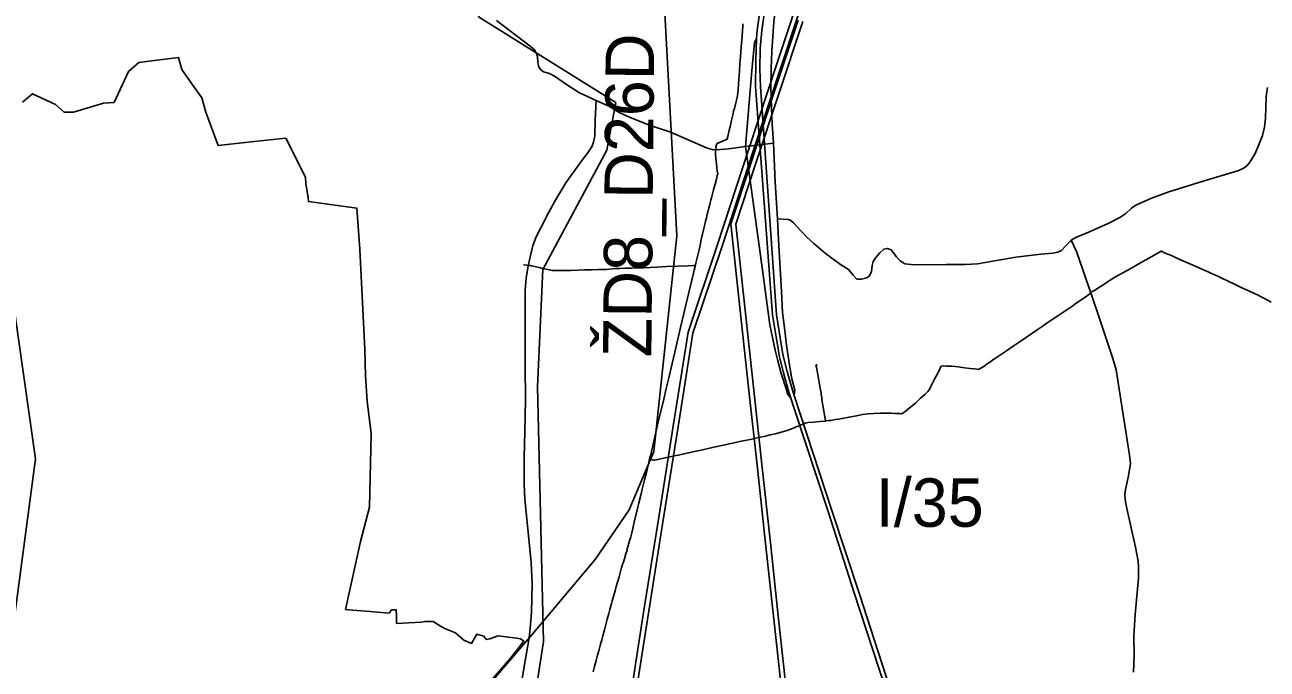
# Model space of a CAD drawing. Extents: x -789162 to -606354, y -1062736 to -945481.
# Drawn here: x -688746 to -684895, y -992137 to -990141 of the extents above; entities that cross this region are included whole.
import ezdxf

# ---------------------------------------------------------------- set-up
doc = ezdxf.new("R2010")
doc.units = 0
for name, color, linetype in [('_SIRSI VZTAHY_CYKLOTRASY MISTNI S', 7, 'Continuous'), ('_SIRSI VZTAHY_ELEKTRICKE VEDENI VN 110 kV S', 7, 'Continuous'), ('_SIRSI VZTAHY_OP vodnich zdroju II stupne', 7, 'Continuous'), ('_SIRSI VZTAHY_SILNICE I a II TRIDY_STAV POPIS', 7, 'Continuous'), ('_SIRSI VZTAHY_SILNICE I TRIDY_STAV', 7, 'Continuous'), ('_SIRSI VZTAHY_SILNICE III TRIDY_STAV', 7, 'Continuous'), ('_SIRSI VZTAHY_VTL PLYNOVOD', 7, 'Continuous'), ('_SIRSI VZTAHY_ZELEZNICE NAVRH', 7, 'Continuous'), ('_SIRSI VZTAHY_ZELEZNICE_NAVRH POPIS', 7, 'Continuous')]:
    doc.layers.add(name, color=color, linetype=linetype)

msp = doc.modelspace()

# ---------------------------------------------------------------- linework, layer by layer
at = {"layer": '_SIRSI VZTAHY_CYKLOTRASY MISTNI S'}
for points in [[(-687483.2, -993028.1), (-687247.3, -992760.3), (-687137.8, -992052), (-687156.9, -991261.1), (-687139.8, -990898.4), (-686941.4, -990528.8), (-686914.1, -990381.7), (-687339.8, -990115.4), (-687139.8, -989851.3), (-686992, -989932.1), (-686499.9, -989984.2), (-686422.9, -989699.9), (-686284.8, -989378.4), (-686007.6, -989239)], [(-688556.1, -989836.5), (-688904.9, -989942.6), (-689006.9, -990177.5), (-688990.4, -990418.2), (-688877.5, -990794.6), (-688784.4, -990982.2), (-688712.6, -991485.2), (-688781.8, -992007.3), (-688812.6, -992131.8), (-688714.4, -992378.9), (-688830.5, -992822.1), (-689079.5, -993178.6), (-688841.2, -993325.5), (-688500.5, -993378.6), (-688063.6, -993516.3), (-687698.6, -993702), (-687435.2, -993863.7)]]:
    msp.add_lwpolyline(points, dxfattribs=at)
at = {"layer": '_SIRSI VZTAHY_ELEKTRICKE VEDENI VN 110 kV S'}
for points in [[(-687451.1, -994051.8), (-687286.8, -993896.2), (-687112.2, -993728.6), (-687063.1, -993431), (-687015, -993140.6), (-686965.9, -992829.5), (-686919.2, -992531.6), (-686876.3, -992269.3), (-686827.9, -991961.7), (-686779.6, -991659.8), (-686736, -991384.3), (-686689.8, -991092.6), (-686599, -990821.5), (-686501.5, -990524.6), (-686415.2, -990261.5), (-686321.1, -989977.3), (-686243.1, -989742.1), (-686159.3, -989488), (-686062.1, -989191.4), (-685979.1, -988943.5), (-685905.5, -988720.6), (-685829.4, -988490.2), (-685756.3, -988268), (-685732.3, -988002.4)], [(-687098.1, -993735.7), (-687048.3, -993433.5), (-687000.2, -993143.1), (-686951.1, -992831.9), (-686904.4, -992534.1), (-686861.5, -992271.8), (-686813.1, -991964.1), (-686764.8, -991662.2), (-686721.2, -991386.8), (-686675.2, -991096.1), (-686584.8, -990826.2), (-686487.3, -990529.2), (-686401, -990266.2), (-686306.9, -989982), (-686228.9, -989746.8), (-686145, -989492.7), (-686047.8, -989196.2), (-685964.9, -988948.3), (-685891.3, -988725.2), (-685815.2, -988494.8), (-685741.5, -988271.1), (-685717.4, -988003.3)], [(-686349, -990126), (-686423, -990349.7), (-686497.1, -990573.9), (-686557.7, -990757.1), (-686529.4, -991016.9), (-686502.4, -991265.1), (-686475.3, -991514.4), (-686450, -991747.7), (-686425.4, -991973.3), (-686402.7, -992181.3), (-686375.2, -992433.8), (-686356.6, -992606.6), (-686325.5, -992891.3), (-686300.1, -993125.2), (-686273.7, -993367.7), (-686249.4, -993590.9)], [(-686349, -990126), (-686423, -990349.7), (-686497.1, -990573.9), (-686557.7, -990757.1), (-686529.4, -991016.9), (-686502.4, -991265.1), (-686475.3, -991514.4), (-686450, -991747.7), (-686425.4, -991973.3), (-686402.7, -992181.3), (-686375.2, -992433.8), (-686356.6, -992606.6), (-686325.5, -992891.3), (-686300.1, -993125.2), (-686273.7, -993367.7), (-686249.4, -993590.9)], [(-686334.7, -990130.7), (-686408.7, -990354.4), (-686482.9, -990578.6), (-686542.4, -990758.7), (-686514.5, -991015.2), (-686487.5, -991263.5), (-686460.4, -991512.7), (-686435, -991746), (-686410.4, -991971.7), (-686387.8, -992179.6), (-686360.3, -992432.1), (-686341.6, -992605), (-686310.6, -992889.6), (-686285.2, -993123.6), (-686258.8, -993366.1), (-686234.5, -993589.2)], [(-686334.7, -990130.7), (-686408.7, -990354.4), (-686482.9, -990578.6), (-686542.4, -990758.7), (-686514.5, -991015.2), (-686487.5, -991263.5), (-686460.4, -991512.7), (-686435, -991746), (-686410.4, -991971.7), (-686387.8, -992179.6), (-686360.3, -992432.1), (-686341.6, -992605), (-686310.6, -992889.6), (-686285.2, -993123.6), (-686258.8, -993366.1), (-686234.5, -993589.2)]]:
    msp.add_lwpolyline(points, dxfattribs=at)
at = {"layer": '_SIRSI VZTAHY_OP vodnich zdroju II stupne'}
msp.add_lwpolyline([(-687328.5, -992205.1), (-687239.4, -992102.3), (-687198.8, -992050.4), (-687209.6, -992043.4), (-687221.7, -992041.3), (-687278.7, -992034.1), (-687304.3, -992043.5), (-687315.5, -992045.7), (-687323.3, -992035.7), (-687345.1, -992029), (-687361.3, -992057.5), (-687384.8, -992048), (-687411, -992024.5), (-687441.8, -992012.8), (-687457.4, -992003.8), (-687480.3, -991989.3), (-687498.3, -991990.1), (-687505.4, -991989.4), (-687516.6, -991991.5), (-687594.3, -991995.5), (-687594.2, -991973.4), (-687594.6, -991953.7), (-687609.2, -991953.7), (-687616.2, -991963.5), (-687665.2, -991960), (-687675.8, -991959.1), (-687742.7, -991953.1), (-687751.8, -991952.3), (-687705.8, -991742.1), (-687677.2, -991635.4), (-687672.7, -991407), (-687684.3, -991307.2), (-687689.5, -991228.9), (-687692.2, -991147.1), (-687707.3, -990835.5), (-687716.3, -990709.3), (-687866.5, -990688.3), (-687867.6, -990675.8), (-687874.7, -990633.6), (-687875.9, -990612.5), (-687893.4, -990578.4), (-687897, -990571.4), (-687936.9, -990491.6), (-688035.5, -990502.7), (-688147, -990515), (-688185.1, -990411.7), (-688197.1, -990366.7), (-688228.6, -990323.2), (-688259, -990279.6), (-688269.5, -990242), (-688352.1, -990252.5), (-688392.7, -990257), (-688424.2, -990285.6), (-688469.3, -990381.8), (-688502.4, -990383.3), (-688595.5, -990411.8), (-688624.1, -990411.8), (-688651.1, -990387.8), (-688721.7, -990354.7), (-688753.3, -990380.3)], dxfattribs=at)
at = {"layer": '_SIRSI VZTAHY_SILNICE I TRIDY_STAV'}
for points in [[(-686465, -990077.6), (-686475.5, -990157.4), (-686478, -990183.3)], [(-686361.2, -991289.1), (-686371.2, -991255.2), (-686382.9, -991215.2), (-686396.5, -991162.1), (-686416.1, -991039.4), (-686466.1, -990332), (-686467.2, -990277.8), (-686466.6, -990213.9), (-686461, -990157.8), (-686450.6, -990077.9)], [(-686478, -990183.3), (-686483.8, -990196), (-686492.1, -990283.6), (-686511.8, -990517.9)], [(-686478, -990183.3), (-686479.6, -990251.6), (-686480.6, -990331.3), (-686428.6, -991039.3), (-686406.9, -991169.8), (-686394.9, -991215.2), (-686377.5, -991278.7), (-686371.7, -991297.6)], [(-686511.8, -990517.9), (-686458.8, -990908.6)], [(-686458.8, -990908.6), (-686436.6, -991070.2), (-686420, -991148.6), (-686412.9, -991177.6), (-686401.3, -991221.5), (-686385.4, -991271.8), (-686381.7, -991285), (-686371.7, -991297.6)], [(-686371.7, -991297.6), (-686361.9, -991326.8), (-686255.6, -991648.6), (-686175.5, -991900.5), (-686079.2, -992193.9), (-686053, -992277.8), (-686041, -992323), (-686028.4, -992380.7), (-686020.2, -992437.3), (-686015.1, -992500.1), (-686014.6, -992512.8)], [(-686002.6, -992506.4), (-686002.8, -992501.9), (-686008.2, -992437.6), (-686014.5, -992385.9), (-686022, -992341.3), (-686034.7, -992287.1), (-686065.4, -992192.7), (-686158.5, -991904.8), (-686243.5, -991648.6), (-686361.2, -991289.1)]]:
    msp.add_lwpolyline(points, dxfattribs=at)
at = {"layer": '_SIRSI VZTAHY_SILNICE III TRIDY_STAV'}
for points in [[(-686094.8, -989270.2), (-686090.6, -989304.6), (-686092.2, -989327.2), (-686099.7, -989348.2), (-686130.8, -989394.2), (-686166.2, -989443.8), (-686190, -989478), (-686213, -989515.3), (-686240.2, -989568.7), (-686254.3, -989597.3), (-686309.8, -989732.6), (-686353.8, -989848), (-686385.5, -989942.6), (-686401.9, -990003.6), (-686413.5, -990057.4), (-686418.6, -990090), (-686423.9, -990131.2), (-686430.7, -990222.5), (-686432.9, -990275.7), (-686433.1, -990332.1), (-686431.8, -990398.7), (-686429.3, -990447.2), (-686425.1, -990507.2)], [(-687284.3, -990127.2), (-687180, -990206.3), (-687165.5, -990219.2), (-687160.5, -990227.3), (-687156.4, -990239.3), (-687155.8, -990256.8), (-687153.3, -990269), (-687147.9, -990279.4), (-687138.6, -990286.5), (-687119.9, -990292), (-687104.3, -990299.6), (-687060.8, -990329.5), (-687026.5, -990351.1), (-686974.6, -990374.7)], [(-685502.3, -990808.5), (-685486, -990798.7), (-685452.6, -990785), (-685385.4, -990755.4), (-685352.3, -990737.4), (-685333.3, -990725.2), (-685315.5, -990708.6), (-685302.2, -990699.8), (-685254.1, -990677.9), (-685200.1, -990657.9), (-685093.9, -990625.1), (-684983.4, -990591.9), (-684966.7, -990584.1), (-684958.5, -990577.9), (-684951.2, -990569.7), (-684933.7, -990541.9), (-684921.8, -990514.4), (-684909.1, -990484.1), (-684903.8, -990457.5), (-684900.7, -990430.2), (-684898.1, -990364.2), (-684896.4, -990347.4), (-684893.6, -990334.6)], [(-686974.6, -990374.7), (-686977.9, -990435.9), (-686979.5, -990484.8), (-686983.3, -990504.3), (-686988.4, -990519.1), (-686999.3, -990534.9), (-687029.4, -990575.4), (-687068.5, -990630.3), (-687099.9, -990682.4), (-687121.2, -990721.7), (-687145.7, -990768), (-687161.4, -990797.7), (-687170.9, -990824.4), (-687186.1, -990887.8), (-687192, -990925.7), (-687194.7, -990962.7), (-687195.2, -991023), (-687194.7, -991198.2), (-687194, -991301.6), (-687195.9, -991402.5), (-687197.9, -991481.1), (-687198, -991565.2), (-687195.9, -991609.8), (-687176.6, -991807), (-687173.5, -991872.8), (-687175.9, -991961.8), (-687179.1, -992010.7), (-687182.8, -992040.8), (-687199.1, -992135.2), (-687211.5, -992211.6)], [(-686974.6, -990374.7), (-686935.4, -990393), (-686903.7, -990412.1), (-686871.9, -990426.7), (-686807.8, -990452.4), (-686747.1, -990471.9), (-686632.5, -990522.2), (-686612.2, -990527.6), (-686589.5, -990527.5), (-686564.8, -990525.3), (-686511.8, -990517.9)], [(-686511.8, -990517.9), (-686425.1, -990507.2)], [(-686425.1, -990507.2), (-686419.9, -990628.1), (-686413.1, -990741.7)], [(-686413.1, -990741.7), (-686378.9, -990743.7), (-686372, -990747.5), (-686363, -990754.6), (-686339.5, -990780.3), (-686321.5, -990798.5), (-686300.6, -990818.1), (-686263.9, -990849.5), (-686217.8, -990883), (-686192.9, -990898.5), (-686178.6, -990916), (-686166.8, -990928.8), (-686152.7, -990928.7), (-686136, -990925), (-686127.6, -990918.6), (-686121.8, -990905.4), (-686119.6, -990886.1), (-686115.9, -990873.7), (-686108.6, -990861.7), (-686096.3, -990848.1), (-686083.6, -990835.8), (-686072.3, -990833.8), (-686060.3, -990838), (-686044.2, -990859.4), (-686032.5, -990872.5), (-686018.4, -990881.4), (-685989.6, -990884.1), (-685890.1, -990883), (-685830.4, -990883.5), (-685793.4, -990881.8), (-685674, -990861.2), (-685596.2, -990851.4), (-685559.5, -990848.5), (-685544.1, -990845.6), (-685532.2, -990839.8), (-685520.3, -990826.6), (-685502.3, -990808.5)], [(-686361.2, -991289.1), (-686358.7, -991273), (-686368.1, -991237.4), (-686374.9, -991201.8), (-686385.2, -991133.5), (-686391.3, -991080), (-686397.4, -991032.2), (-686400.2, -990966.9), (-686410.1, -990807.3), (-686413.1, -990741.7)], [(-685309.7, -992146.9), (-685307.5, -992094.3), (-685308.8, -992033.7), (-685304.4, -991967.6), (-685299.6, -991911.7), (-685293.9, -991855.2), (-685294.2, -991821.9), (-685295.5, -991802.9), (-685303.4, -991759), (-685330.4, -991640), (-685334.5, -991619), (-685336.7, -991598.7), (-685334.1, -991580.5), (-685325.1, -991538.1), (-685318.9, -991500.4), (-685321.9, -991474.6), (-685330.7, -991414.2), (-685343.1, -991335.8), (-685362.8, -991210.1), (-685373.9, -991174.5), (-685421.2, -991032.6), (-685447.2, -990956.8), (-685485.7, -990843.2), (-685502.3, -990808.5)]]:
    msp.add_lwpolyline(points, dxfattribs=at)
at = {"layer": '_SIRSI VZTAHY_VTL PLYNOVOD'}
for points in [[(-686548.8, -990407.7), (-686546.4, -990399.9), (-686541.1, -990378.2), (-686537.9, -990365.5), (-686535.6, -990351.5), (-686533.8, -990327.5), (-686532.7, -990307.3), (-686532.2, -990300.3), (-686530.8, -990282.3), (-686529.3, -990261.9), (-686527.4, -990239.6), (-686525.3, -990209.2), (-686522.7, -990177.2), (-686521.3, -990157.7), (-686520.6, -990146.5), (-686520, -990137.6)], [(-686668, -990887), (-686667.6, -990885.9), (-686667.4, -990885.4), (-686666.9, -990884.1), (-686665.8, -990879), (-686660.6, -990858.7), (-686655.9, -990838.2), (-686653, -990824.9), (-686650.1, -990811.4), (-686647, -990796.7), (-686645.6, -990789.9), (-686645.6, -990789.7), (-686644.2, -990784.8), (-686641.9, -990775.5), (-686639.6, -990763.9), (-686635.6, -990749), (-686632.9, -990738.3), (-686630.4, -990727.8), (-686627.8, -990717.6), (-686625.3, -990708.2), (-686622.4, -990697.4), (-686619.1, -990683.5), (-686617.6, -990677.3), (-686615.4, -990668.4), (-686611.3, -990652.2), (-686606.6, -990634.9), (-686602.4, -990618.6), (-686599.6, -990608.1), (-686598.2, -990602), (-686599.5, -990592.9), (-686600.7, -990582.5), (-686602.8, -990563.6), (-686605.1, -990542.2), (-686605.3, -990540.5), (-686604.6, -990533.1), (-686603.5, -990523.6), (-686603.8, -990519.6), (-686603.9, -990518.5), (-686603, -990515.9), (-686601.4, -990509.1), (-686600.8, -990508.4), (-686594.9, -990506.3), (-686583.2, -990501.4), (-686578.4, -990499.3), (-686569, -990495.1), (-686568.6, -990493.8), (-686567, -990487), (-686562.3, -990467.2), (-686559.7, -990457.2), (-686555, -990436.3), (-686550.4, -990415.1), (-686549, -990408.8), (-686548.8, -990408), (-686548.8, -990407.7)], [(-686548.8, -990407.7), (-686548.9, -990407.6)], [(-684882.6, -990999.7), (-684903.1, -990988.8), (-684915.5, -990982.3), (-684925.4, -990977.9), (-684934.5, -990973.7), (-684949.7, -990966.5), (-684973.2, -990955.3), (-684989.8, -990947.4), (-685004.2, -990940.5), (-685008, -990938.9), (-685015.7, -990935), (-685033.2, -990926.6), (-685047.7, -990920), (-685055.5, -990916.3), (-685065.8, -990912.1), (-685078.4, -990906.1), (-685090.1, -990900.7), (-685110.7, -990891.5), (-685134.9, -990881.2), (-685163.4, -990868.8), (-685183.7, -990860.1), (-685192.1, -990856), (-685211.1, -990847.8), (-685223, -990842.1), (-685223.6, -990841.9), (-685224.2, -990842.2), (-685243.7, -990853.3), (-685262, -990864), (-685280.4, -990874.4), (-685300, -990885.5), (-685321.6, -990897.9), (-685340, -990908.2), (-685355.5, -990916.9), (-685372, -990926.1), (-685380.1, -990930.9), (-685387.2, -990935.4), (-685401.8, -990945.1), (-685416.7, -990955.1), (-685430.8, -990964), (-685437.5, -990967.2), (-685444.2, -990973), (-685448, -990976.1), (-685466.9, -990990.1), (-685486.7, -991003.3), (-685500.9, -991013.2), (-685522.2, -991027.6), (-685543.9, -991042), (-685568.2, -991058.5), (-685576.8, -991064.7), (-685589.7, -991073.5), (-685604.7, -991083.7), (-685621.8, -991095.1), (-685641.4, -991108.2), (-685663.8, -991123.7), (-685682.6, -991136.4), (-685703.1, -991150.6), (-685725.3, -991165.8), (-685740.3, -991176.2), (-685742.3, -991177.3), (-685751.9, -991184), (-685763.5, -991191.7), (-685773.7, -991199.1), (-685786.4, -991206.3), (-685790.9, -991208.3), (-685794.8, -991207.9), (-685801.8, -991207.2), (-685815.5, -991205.9), (-685833.5, -991203.3), (-685853.1, -991200.8), (-685872.6, -991198.9), (-685880.8, -991198.1), (-685884.9, -991198), (-685885, -991198), (-685889.5, -991198), (-685897.1, -991197.9), (-685904, -991198.4), (-685905.7, -991198.6), (-685906.6, -991200), (-685908.6, -991204.6), (-685916.3, -991220.3), (-685924.8, -991237.2), (-685932.1, -991251), (-685938.4, -991263.2), (-685941.8, -991270.6), (-685947, -991276.7), (-685955.3, -991285), (-685970.2, -991299.1), (-685985.6, -991312.9), (-686004.3, -991328.6), (-686018.3, -991340.1), (-686026.1, -991345.6), (-686026.9, -991345.8), (-686027.8, -991345.7), (-686035.1, -991345.1), (-686042.9, -991344.7), (-686049.6, -991344.7), (-686059.1, -991344.1), (-686061.8, -991344.2), (-686063, -991344.2), (-686063.2, -991344.2), (-686065.9, -991344.1), (-686075, -991344), (-686093.4, -991343.9), (-686113.8, -991345.2), (-686131.4, -991346.6), (-686149.4, -991348.6), (-686167.8, -991351.9), (-686190.8, -991356.2), (-686212.1, -991360.7), (-686223.6, -991363), (-686233.6, -991364.2), (-686246.9, -991366.7), (-686253.7, -991367.3), (-686263.7, -991368.4), (-686263.8, -991368.4)], [(-687199.9, -990883.9), (-687199.3, -990884), (-687199.1, -990884), (-687199, -990884), (-687191, -990885.2), (-687179.7, -990886.8), (-687176.9, -990887.2), (-687176.7, -990887.2), (-687176.7, -990887.2), (-687176.6, -990887.2), (-687174.5, -990887.5), (-687170.1, -990888.6), (-687161.4, -990890.9), (-687151.7, -990892.9), (-687140.1, -990895.5), (-687119.4, -990900.4), (-687111.4, -990901.8), (-687105.4, -990902.2), (-687105.2, -990902.2), (-687097.6, -990902.4), (-687087.8, -990902.5), (-687078.9, -990902.3), (-687078.9, -990902.3), (-687053.5, -990902.3), (-687030.3, -990901), (-687011.5, -990900.2), (-686989.7, -990899.6), (-686989.6, -990899.6), (-686968.5, -990899.3), (-686955.4, -990899.2), (-686943.3, -990898.9), (-686934.8, -990898.1), (-686915.5, -990896.3), (-686901.3, -990895.7), (-686884.8, -990895.2), (-686878.7, -990895), (-686878.6, -990895), (-686878.3, -990895), (-686864.6, -990894.3), (-686846.5, -990893.6), (-686827.2, -990893.3), (-686806.9, -990892.4), (-686786.8, -990891.6), (-686755.6, -990889.9), (-686721, -990888.8), (-686689.7, -990887.4), (-686672.4, -990886.7), (-686669.9, -990886.8), (-686669.5, -990886.9)], [(-686809.6, -991486.4), (-686808.4, -991481.9), (-686806, -991473.1), (-686802.6, -991458), (-686799.4, -991445.4), (-686793.2, -991417.5), (-686790.3, -991404.4), (-686782.5, -991371.2), (-686775, -991338.9), (-686765.6, -991301.1), (-686757.7, -991267.6), (-686749.1, -991230.7), (-686739, -991190.7), (-686730.8, -991155.6), (-686721.5, -991115.2), (-686713.1, -991078.4), (-686702.9, -991035.1), (-686694.7, -990999.8), (-686687.1, -990965.7), (-686679.8, -990935.7), (-686673.6, -990910.5), (-686671.1, -990900.6), (-686668.6, -990890.1), (-686668.4, -990888.3), (-686668.4, -990888.3), (-686668.3, -990888), (-686668.3, -990888), (-686668, -990887)], [(-686669.5, -990886.9), (-686669.5, -990887.3), (-686669, -990887.3), (-686668.5, -990887.3), (-686668.5, -990886.9)], [(-686669.5, -990886.9), (-686669.3, -990886.9)], [(-686669.3, -990886.9), (-686669.3, -990886.5), (-686669.2, -990886.5), (-686669, -990886.5), (-686668.8, -990886.5), (-686668.7, -990886.5), (-686668.7, -990886.9)], [(-686668.7, -990886.9), (-686669, -990886.9), (-686669.3, -990886.9)], [(-686668.5, -990886.9), (-686668.7, -990886.9)], [(-686668, -990887), (-686668.3, -990886.9), (-686668.5, -990886.9)], [(-686293.1, -991197.5), (-686293.9, -991197.6), (-686293.9, -991197.8), (-686293.8, -991198.2), (-686293.7, -991198.4), (-686292.9, -991198.3)], [(-686290.3, -991196.2), (-686290.6, -991195), (-686290.9, -991194.6), (-686291.4, -991194.6), (-686292, -991194.8), (-686292.2, -991194.8), (-686292.4, -991194.9), (-686293.1, -991195.1), (-686293.5, -991195.4), (-686293.5, -991195.8), (-686293.2, -991197), (-686293.1, -991197.2), (-686293.1, -991197.5)], [(-686293.1, -991197.5), (-686293, -991197.9), (-686292.9, -991198.3)], [(-686263.8, -991367.8), (-686264.1, -991367.3), (-686264.1, -991367.2), (-686264.9, -991361.9), (-686266.9, -991350.2), (-686267.8, -991344.2), (-686268.9, -991338.2), (-686270.3, -991330.2), (-686273.2, -991314.1), (-686275.1, -991303), (-686276, -991296.2), (-686276.6, -991290.9), (-686277.4, -991285), (-686277.7, -991283.1), (-686278.8, -991276.3), (-686279.6, -991271.7), (-686283.7, -991249.6), (-686285.6, -991236.6), (-686286.4, -991231.7), (-686288.8, -991218.4), (-686290.8, -991208.1), (-686292.1, -991202.1), (-686292.4, -991201.2), (-686292.9, -991198.5), (-686292.9, -991198.3)], [(-686804.9, -991487.7), (-686803.9, -991488), (-686801.8, -991488.5), (-686795.2, -991490.2), (-686793.7, -991490.3), (-686792.7, -991489.9), (-686780.1, -991486.9), (-686760.5, -991482.6), (-686737.6, -991477.6), (-686715.4, -991472.8), (-686694.1, -991468.3), (-686687.4, -991467), (-686675.7, -991464.2), (-686659.8, -991460.4), (-686636.5, -991455.3), (-686610.1, -991449.4), (-686585.7, -991443.9), (-686562.1, -991439), (-686543.3, -991435.2), (-686525.4, -991431.4), (-686507.8, -991427.6), (-686496.4, -991425.4), (-686471.3, -991419.5), (-686450.4, -991414.9), (-686442.8, -991413.2), (-686435.2, -991411.5), (-686418.7, -991407.7), (-686401.8, -991403.3), (-686379.9, -991396.6), (-686369.3, -991392.6), (-686361.6, -991389.3), (-686355.1, -991386.7), (-686349.1, -991384.5), (-686326.8, -991375.2), (-686322.7, -991373.7), (-686317.6, -991373.2), (-686301.6, -991371.9), (-686281.3, -991370.3), (-686265.1, -991368.6), (-686264.8, -991368.5), (-686264.6, -991368.5)], [(-686264.6, -991368.5), (-686264.6, -991368.2), (-686264.6, -991367.9), (-686263.8, -991367.8)], [(-686264.6, -991368.5), (-686263.8, -991368.4)], [(-686263.8, -991367.8), (-686263.8, -991368.1), (-686263.8, -991368.4)], [(-686984.4, -992146.1), (-686979.9, -992129.2), (-686974.9, -992110.8), (-686970.7, -992094.5), (-686966.5, -992081), (-686962.1, -992063.8), (-686957.3, -992046.1), (-686954.1, -992034), (-686949.4, -992015.8), (-686944.7, -991998.9), (-686940.4, -991982.4), (-686935.7, -991964.7), (-686932.5, -991952.5), (-686927.4, -991934.5), (-686925.1, -991925.7), (-686924.1, -991922.2), (-686919.3, -991905.5), (-686916.2, -991894.7), (-686912.5, -991880.9), (-686904.1, -991851.3), (-686896, -991822.6), (-686887.4, -991796), (-686882.7, -991779.6), (-686879.1, -991769.1), (-686879, -991768.7), (-686878.4, -991764.3), (-686875.3, -991754), (-686871.7, -991740), (-686868, -991727), (-686864.9, -991714.8), (-686861.4, -991701.2), (-686855.8, -991676.9), (-686848.2, -991645.2), (-686842.6, -991622.3), (-686836.8, -991598.5), (-686832.3, -991579.8), (-686825.1, -991551), (-686819.4, -991528.1), (-686813.9, -991505.7), (-686811.6, -991497), (-686810.3, -991490.9), (-686809.8, -991488.1), (-686809.6, -991486.4)], [(-686809.6, -991486.4), (-686806.9, -991487.2), (-686806, -991487.4)], [(-686804.9, -991487.7), (-686804.9, -991488), (-686805, -991488.3), (-686805.2, -991488.2), (-686805.6, -991488.1), (-686806, -991488.1), (-686806.2, -991488), (-686806, -991487.4)], [(-686806, -991487.4), (-686805.4, -991487.6), (-686804.9, -991487.7)]]:
    msp.add_lwpolyline(points, dxfattribs=at)
at = {"layer": '_SIRSI VZTAHY_ZELEZNICE NAVRH'}
for points in [[(-686795.8, -991462.7), (-686725.1, -990794.1), (-686770.6, -989950.2), (-686813.7, -988842.7), (-686780.8, -988439.8), (-686796, -987844.3), (-686704.8, -987423.6), (-686618.7, -987223.4), (-686441.4, -986992.8), (-686276.8, -986729.2), (-686099.6, -986105.8), (-686097, -985900.5), (-686150.2, -985761.2), (-686352.8, -985497.6), (-686628.8, -985211.2), (-686940.3, -984826), (-687246.7, -984615.7), (-687846.9, -984314.1), (-688181.2, -984015.1), (-688416.7, -983809.8), (-688553.5, -983657.8), (-688738.3, -983432.2)], [(-686795.8, -991462.7), (-686873.2, -991644.1), (-686977.6, -991797.7), (-687174.2, -992031.1), (-687364.7, -992252.3), (-687573.6, -992584.1), (-687816, -992972.3), (-687819.7, -992978.2), (-687886.7, -993090.9), (-687939.6, -993190.2), (-687989.9, -993295.9), (-688036.3, -993406.7), (-688078.3, -993522.7), (-688120.9, -993657.6), (-688164.5, -993801), (-688198.7, -993911.9), (-688235.7, -994018.6), (-688281.7, -994126.7), (-688337, -994233.6), (-688399.2, -994334.8), (-688457.1, -994415.8), (-688533, -994508.1), (-688628.5, -994606.8), (-688727.7, -994693.5)]]:
    msp.add_lwpolyline(points, dxfattribs=at)

# ---------------------------------------------------------------- texts
at = {"layer": '_SIRSI VZTAHY_SILNICE I a II TRIDY_STAV POPIS'}
msp.add_text('I/35', height=150, dxfattribs=at).set_placement((-686108.3, -991696.2))
at = {"layer": '_SIRSI VZTAHY_ZELEZNICE_NAVRH POPIS'}
msp.add_text('ŽD8_D26D', height=150, rotation=89.4958, dxfattribs=at).set_placement((-686803.9, -991171.3))

doc.saveas('drawing.dxf')
